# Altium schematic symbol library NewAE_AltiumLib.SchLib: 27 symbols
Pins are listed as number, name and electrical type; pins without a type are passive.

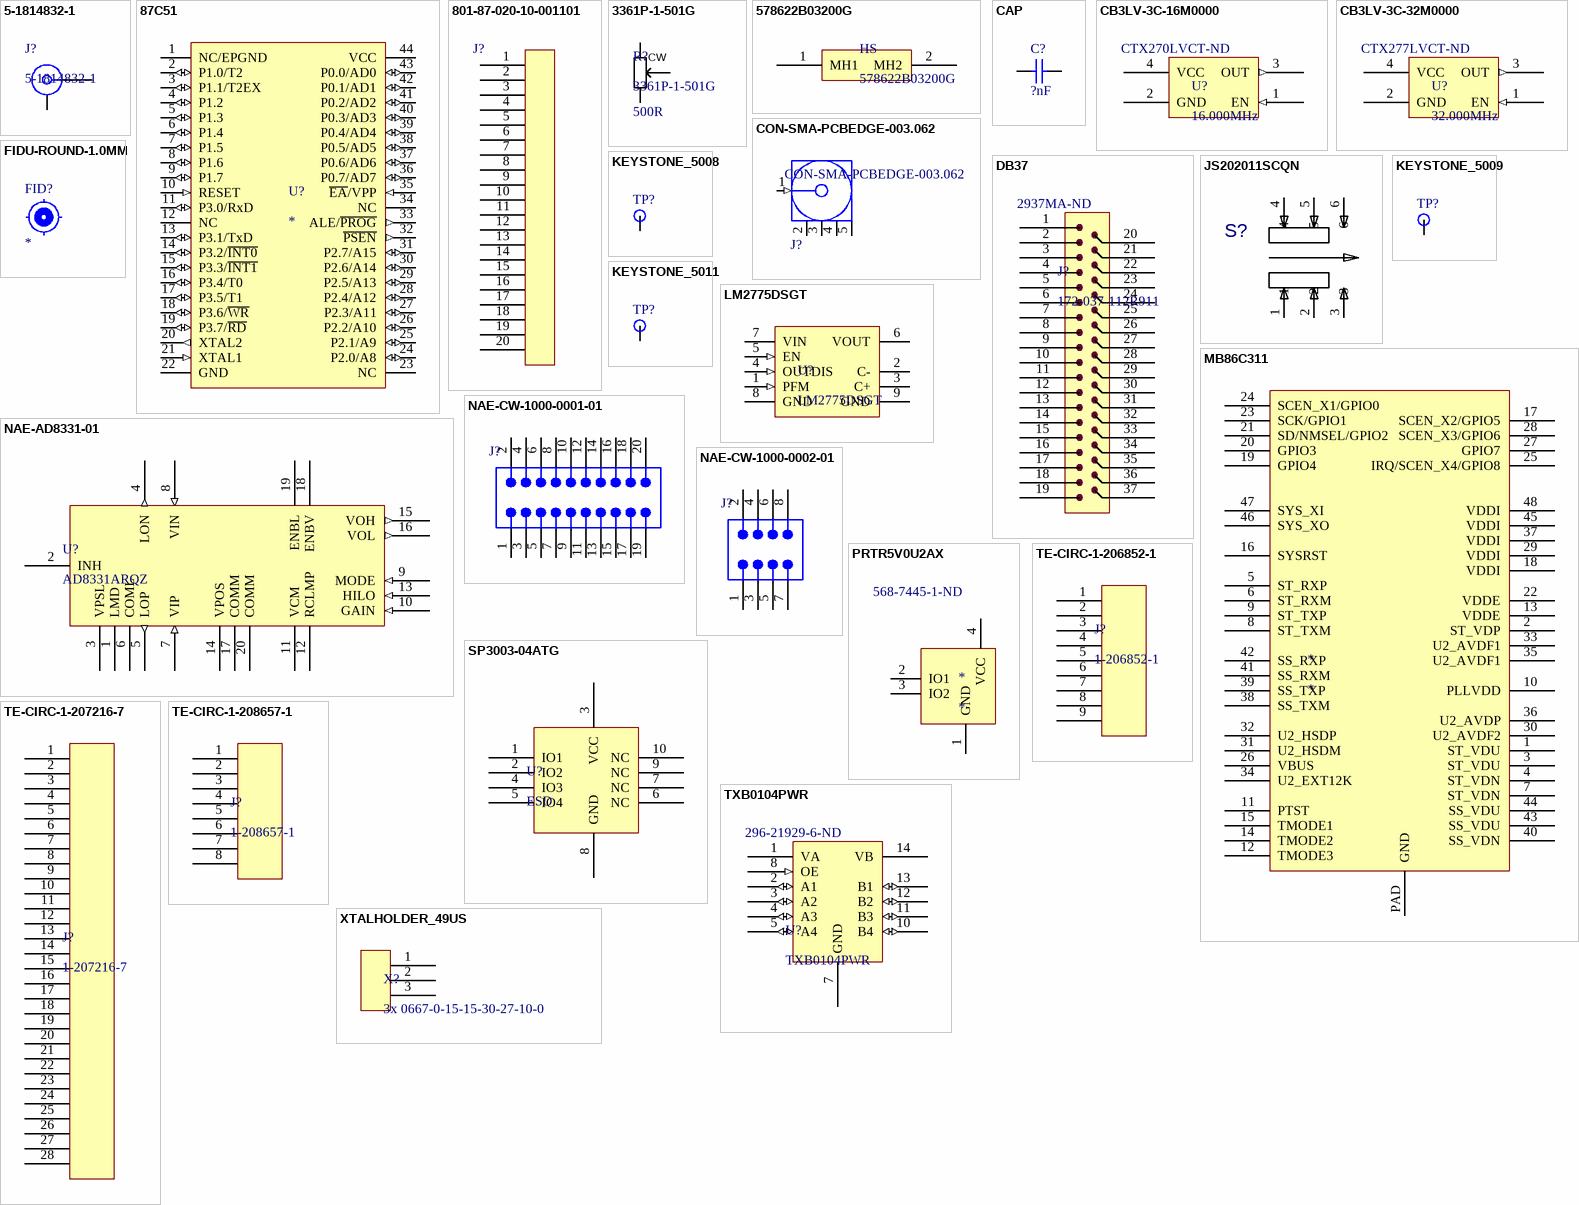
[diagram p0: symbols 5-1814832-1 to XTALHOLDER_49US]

## 5-1814832-1
designator J?
SMA, Vert; Manufacture 1: TE Connectivity
footprint SMA_VERT_1.65MMHOLE (SMA Straight Jack, 6.35x6.35x9.5mm, Rosenberger Recommended)
pins: 1, MH

## 87C51
designator U?
footprint PLCC44_SOCKET
pins: 1 NC/EPGND "VSS1 for EEPROM Only", 2 P1.0/T2 (io), 3 P1.1/T2EX (io), 4 P1.2 (io), 5 P1.3 (io), 6 P1.4 (io), 7 P1.5 (io), 8 P1.6 (io), 9 P1.7 (io), 10 RESET (in), 11 P3.0/RxD (io), 12 NC (hiz), 13 P3.1/TxD (io), 14 P3.2/~{INT0} (io), 15 P3.3/~{INT1} (io), 16 P3.4/T0 (io), 17 P3.5/T1 (io), 18 P3.6/~{WR} (io), 19 P3.7/~{RD} (io), 20 XTAL2 (out), 21 XTAL1 (in), 22 GND (power), 23 NC (hiz), 24 P2.0/A8 (io), 25 P2.1/A9 (io), 26 P2.2/A10 (io), 27 P2.3/A11 (io), 28 P2.4/A12 (io), 29 P2.5/A13 (io), 30 P2.6/A14 (io), 31 P2.7/A15 (io), 32 ~{PSEN} (out), 33 ALE/~{PROG} (out), 34 NC (hiz), 35 ~{EA}/VPP (in), 36 P0.7/AD7 (io), 37 P0.6/AD6 (io), 38 P0.5/AD5 (io), 39 P0.4/AD4 (io), 40 P0.3/AD3 (io), 41 P0.2/AD2 (io), 42 P0.1/AD1 (io), 43 P0.0/AD0 (io), 44 VCC (power)

## 801-87-020-10-001101
designator J?, comment 20-Pin Header  (value not drawn)
1x20 Header, Machined; Manufacture Part Number 1: 801-87-020-10-001101; Manufacture 1: Preci-Dip SA
footprint 801-87-020-10-001101
pins: 1, 2, 3, 4, 5, 6, 7, 8, 9, 10, 11, 12, 13, 14, 15, 16, 17, 18, 19, 20

## 3361P-1-501G
designator R?  value 500R
500 ohm, single-turn trimmer; Manufacture 1: Bourns Inc; Manufacture Part Number 1: 3361P-1-501GLF
footprint BOURNS-3361P
pins: CCW 1, CW 3, W 2

## 578622B03200G
designator HS
Aavid Thermal 578622B03200G Dual-TO220 Heatsink
footprint 578622B03200G (Aavid Dual TO220 Heatsink 578622B03200G)
pins: 1 MH1, 2 MH2

## CAP
designator C?, comment ?nF
Ceramic Capacitors; Case-EIA: 0402; Case-Metric: 1005; Tolerance: Â±10%; Rated Voltage: 16 V
footprint CAPC0402_M (Chip Capacitor, 2-Leads, Body 0402, IPC Medium Density)
footprint CAPC0603_M
pins: 1, 2
1 alternate drawing of the same symbol

## CB3LV-3C-16M0000
designator U?, comment 16.000MHz  Supplier Part Number 1: CTX270LVCT-ND
16MHz, 3.3V OSC, 5x7mm
footprint 7x5mm XTAL
pins: 1 EN (in), 2 GND (power), 3 OUT (out), 4 VCC (power)

## CB3LV-3C-32M0000
designator U?, comment 32.000MHz  Supplier Part Number 1: CTX277LVCT-ND
32MHz, 3.3V OSC, 5x7mm
footprint 7x5mm XTAL
pins: 1 EN (in), 2 GND (power), 3 OUT (out), 4 VCC (power)

## CON-SMA-PCBEDGE-003.062
designator J?
SMA Female Edge Mount Connector for 0.062" Thick Board; PCB_Layout: Pads complies with manufacturer's recommendation.
footprint CON-SMAM-PCB-EDGE062 (Connector, SMA Edge Mount for 0.062" Thick Board, 5-Lead)
pins: 1 Signal (in) "Signal Pin", 2 GND (power), 3 GND (power), 4 GND (power), 5 GND (power)

## DB37
designator J?, comment 172-037-112R911  Supplier Part Number 1: 2937MA-ND
footprint 172-037-112R911 (DB37 Male Header Board Mount)
pins: 1, 2, 3, 4, 5, 6, 7, 8, 9, 10, 11, 12, 13, 14, 15, 16, 17, 18, 19, 20, 21, 22, 23, 24, 25, 26, 27, 28, 29, 30, 31, 32, 33, 34, 35, 36, 37

## FIDU-ROUND-1.0MM
designator FID?  (no BOM)
ROUND FIDUCIAL
footprint FIDU-ROUND-1.0mm

## JS202011SCQN
designator S?  (value not drawn)
DPDT SMD Switch, 300mA; Manufacture 1: C&K Components
footprint SW_JS202011SCQN
pins: 1, 2, 3, 4, 5, 6

## KEYSTONE_5008
designator TP?, comment 5008  (value not drawn)
TEST POINT PC COMPACT .063"D ORG
footprint KEYSTONE5008 (TEST POINT PC MULTI PURPOSE ORG)
pins: 1

## KEYSTONE_5009
designator TP?, comment 5009  (value not drawn)
TEST POINT PC COMPACT .063"D YEL
footprint KEYSTONE5009 (TEST POINT PC MULTI PURPOSE YEL)
pins: 1

## KEYSTONE_5011
designator TP?, comment 5011  (value not drawn)
TEST POINT PC MULTI PURPOSE BLK
footprint KEYSTONE5011 (TEST POINT PC MULTI PURPOSE BLK)
pins: 1

## LM2775DSGT
designator U?
DC-DC 2.7-5V to 5V
footprint S-PWSON-N8 (SON, 8-Leads, Body 2.00x2.00mm, Pitch 0.50mm, Thermal Pad 1.60x0.69mm, IPC Low Density)
pins: 1 PFM (in), 2 C-, 3 C+, 4 OUTDIS (in), 5 EN (in), 6 VOUT (power), 7 VIN (power), 8 GND (power), 9 GND (power)

## MB86C311
designator *
footprint QFN48_6x6_0.4mm_HANDSOLDERING (QFN48, 6x6 body, hand soldering (long leads))
pins: 1 ST_VDU, 2 ST_VDP, 3 ST_VDU, 4 ST_VDN, 5 ST_RXP, 6 ST_RXM, 7 ST_VDN, 8 ST_TXM, 9 ST_TXP, 10 PLLVDD, 11 PTST, 12 TMODE3, 13 VDDE, 14 TMODE2, 15 TMODE1, 16 SYSRST, 17 SCEN_X2/GPIO5, 18 VDDI, 19 GPIO4, 20 GPIO3, 21 SD/NMSEL/GPIO2, 22 VDDE, 23 SCK/GPIO1, 24 SCEN_X1/GPIO0, 25 IRQ/SCEN_X4/GPIO8, 26 VBUS, 27 GPIO7, 28 SCEN_X3/GPIO6, 29 VDDI, 30 U2_AVDF2, 31 U2_HSDM, 32 U2_HSDP, 33 U2_AVDF1, 34 U2_EXT12K, 35 U2_AVDF1, 36 U2_AVDP, 37 VDDI, 38 SS_TXM, 39 SS_TXP, 40 SS_VDN, 41 SS_RXM, 42 SS_RXP, 43 SS_VDU, 44 SS_VDU, 45 VDDI, 46 SYS_XO, 47 SYS_XI, 48 VDDI, PAD GND

## NAE-AD8331-01
designator U?, comment AD8331ARQZ
AD8331 LNA
footprint SOP64P600X175-20N (SOP, 20-Leads, Body 8.66x3.91mm, Pitch 0.64mm, IPC Medium Density)
pins: 1 LMD, 2 INH, 3 VPSL (power), 4 LON (out), 5 LOP (out), 6 COML, 7 VIP (in), 8 VIN (in), 9 MODE (in), 10 GAIN (in), 11 VCM, 12 RCLMP, 13 HILO (in), 14 VPOS (power), 15 VOH (out), 16 VOL (out), 17 COMM (power), 18 ENBV, 19 ENBL, 20 COMM (power)

## NAE-CW-1000-0001-01
designator J?
20 Pin R/A Shrouded Header; Manufacturer: Samtec; PartNumber: HW-10-09-F-D-675-055; Pitch: 2.54 mm
footprint NAE-PCB-CW-1000-0001-01 (High Temp Terminal Body, 2x10 Pins, R/A, 2.54mm Pitch, Male)
pins: 1, 2, 3, 4, 5, 6, 7, 8, 9, 10, 11, 12, 13, 14, 15, 16, 17, 18, 19, 20

## NAE-CW-1000-0002-01
designator J?
8 Pin R/A Shrouded Header; Manufacturer: Samtec; PartNumber: HW-10-09-F-D-675-055; Pitch: 2.54 mm
footprint NAE-PCB-CW-1000-0002-01 (High Temp Terminal Body, 2x4 Pins, R/A, 2.54mm Pitch, Male)
pins: 1, 2, 3, 4, 5, 6, 7, 8

## PRTR5V0U2AX
designator *  Supplier Part Number 1: 568-7445-1-ND
footprint SOT143B (SOT143, 4-Leads, Body 2.92x2.37mm, Pitch 1.90mm, IPC Medium Density)
pins: 1 GND (power), 2 IO1 (power), 3 IO2 (power), 4 VCC (power)

## SP3003-04ATG
designator U?, comment ESD
SP3003-04ATG
footprint MSOP10
pins: 1 IO1, 2 IO2, 3 VCC (power), 4 IO3, 5 IO4, 6 NC, 7 NC, 8 GND (power), 9 NC, 10 NC

## TE-CIRC-1-206852-1
designator J?, comment 1-206852-1
TE Circular Connector, 9-Pin Male
footprint TE_1-206852-1 (TE 1-206852-1 (9-Pin Male Circular))
pins: 1, 2, 3, 4, 5, 6, 7, 8, 9

## TE-CIRC-1-207216-7
designator J?, comment 1-207216-7
TE Circular Connector, 28-Pin Female
footprint TE_1-207216-7 (TE Round 1-207216-7)
pins: 1, 2, 3, 4, 5, 6, 7, 8, 9, 10, 11, 12, 13, 14, 15, 16, 17, 18, 19, 20, 21, 22, 23, 24, 25, 26, 27, 28

## TE-CIRC-1-208657-1
designator J?, comment 1-208657-1
TE Circular Connector, 8-Pin Female
footprint TE_1-208657-1
pins: 1, 2, 3, 4, 5, 6, 7, 8

## TXB0104PWR
designator U?  Supplier Part Number 1: 296-21929-6-ND
footprint TSSOP65P640X120-14N (TSSOP, 14-Leads, Body 5.0x4.5mm (max), Pitch 0.65mm, IPC Medium Density)
pins: 1 VA (power), 2 A1 (io), 3 A2 (io), 4 A3 (io), 5 A4 (io), 7 GND (power), 8 OE (in), 10 B4 (io), 11 B3 (io), 12 B2 (io), 13 B1 (io), 14 VB (power)

## XTALHOLDER_49US
designator X?, comment 3x 0667-0-15-15-30-27-10-0
XTAL Holder built using 3x 0667-0-15-15-30-27-10-0
footprint HC49U_SOCKET (3x 0667-0-15-15-30-27-10-0)
pins: 1, 2, 3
